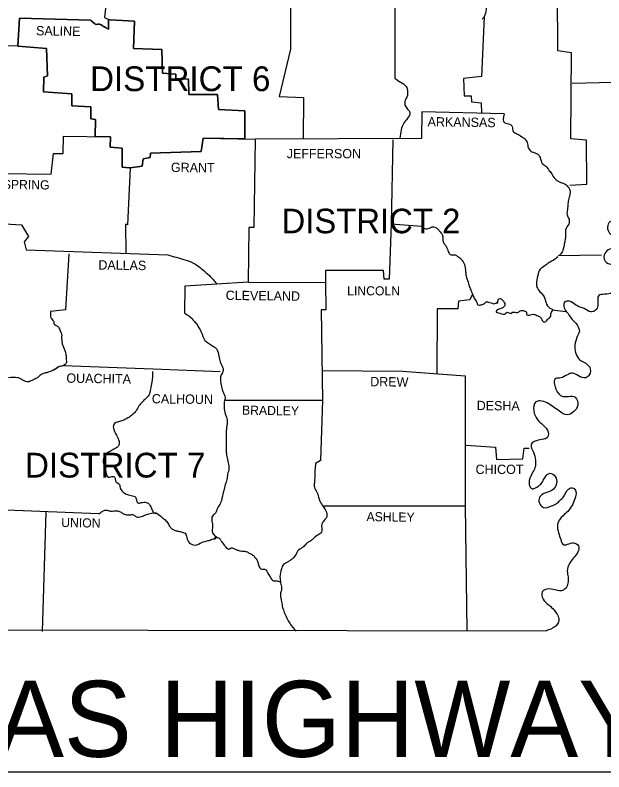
# Model space of a CAD drawing. Extents: x -42408 to 34530, y -43140 to 20491.
# Drawn here: x -16626 to -15135, y 2539 to 4456 of the extents above; entities that cross this region are included whole.
import ezdxf

# ---------------------------------------------------------------- set-up
doc = ezdxf.new("R2010")
doc.units = 0
for name, color, linetype in [('1', 7, 'Continuous'), ('2', 7, 'Continuous'), ('3', 7, 'Continuous'), ('S_MISC_BOUNDARY', 7, 'Continuous')]:
    doc.layers.add(name, color=color, linetype=linetype)

msp = doc.modelspace()

# ---------------------------------------------------------------- linework, layer by layer
at = {"layer": '1'}
for p, q in [((-15250.6, 3847.5), (-15140.6, 3849.1)), ((-17741.9, 2539.3), (-14228.8, 2539.3))]:
    msp.add_line(p, q, dxfattribs=at)
for points in [[(-15743.2, 4605.5), (-15742.1, 4509), (-15664.5, 4507.4), (-15664, 4296)], [(-15952.9, 4581.7), (-15928.7, 4580), (-15928.1, 4369.8), (-15956.8, 4250.4), (-15895.7, 4247.6), (-15896.2, 4142.4)], [(-16215.4, 4527.2), (-16255, 4531.6), (-16253.4, 4516.7), (-16325.5, 4514), (-16327.7, 4492.5), (-16395.4, 4488.7), (-16399.2, 4450.1), (-16389.3, 4445.2), (-16389.3, 4420.6)], [(-15220.9, 4025.3), (-15178, 4028), (-15178.6, 4139.7), (-15218.7, 4142.5), (-15216.5, 4361), (-15251.2, 4365.9), (-15252.3, 4512.9), (-14782.8, 4516.2)], [(-16434.5, 4443), (-16614.4, 4448.5), (-16619.4, 4377.5), (-16839.5, 4378.6), (-16840.6, 4354.9)], [(-15438.3, 4451.8), (-15444.9, 4301), (-15490.1, 4296), (-15489, 4251.5), (-15470.8, 4252), (-15470.2, 4236.6), (-15445.5, 4233.8), (-15444.7, 4207.3)], [(-16385.5, 4444.6), (-16323.8, 4440.8), (-16326, 4372), (-16253.9, 4369.2), (-16252.8, 4309.2), (-16218.7, 4306.5), (-16218.7, 4296), (-16186.8, 4293.8), (-16185.7, 4255.3), (-16113.1, 4255.3), (-16110.9, 4217.3), (-16043.7, 4214), (-16044.3, 4142.5)], [(-16617.9, 4377.4), (-16546.2, 4371.4), (-16544, 4302.1), (-16553.3, 4298.8), (-16554.4, 4261.9), (-16482.3, 4257), (-16482.3, 4226.7), (-16434.5, 4223.9), (-16433.9, 4193.7), (-16422.4, 4192), (-16422.9, 4148.5)], [(-15215.4, 4283.4), (-14905, 4291.1)], [(-15387.7, 4205.8), (-15595.7, 4211.3), (-15596.8, 4143.6), (-16017.8, 4141.9)], [(-16849.4, 4057.7), (-16534.6, 4053.3), (-16528.6, 4105.6), (-16503.8, 4105.6), (-16503.3, 4149.6), (-16384.4, 4148), (-16385.5, 4121.6), (-16354.7, 4119.4), (-16354.7, 4070.9), (-16336, 4069.4)], [(-16334.8, 4069.3), (-16304, 4073.7), (-16301.8, 4092.4), (-16283.7, 4095.7), (-16282.6, 4106.7), (-16154.3, 4110.6), (-16149.4, 4144.1), (-16017.8, 4141.9)], [(-16017.8, 4140.8), (-16021.1, 3918.5), (-16033.8, 3917.9), (-16035.5, 3779.8)], [(-15668.9, 4140.3), (-15673.3, 3927.3), (-15596.8, 3921.2)], [(-16334.8, 4069.3), (-16341.4, 3925.1), (-16346.4, 3926.7), (-16345.9, 3851.9)], [(-16914.4, 3910.8), (-16915.5, 3941.1), (-16906.7, 3941.6), (-16901.2, 4012.6), (-16816.4, 4007.1), (-16818.6, 3963.6), (-16709.1, 3957.6), (-16708.5, 3931.2), (-16609.5, 3925.1), (-16592.4, 3895.4), (-16602.9, 3882.2), (-16597.9, 3861.8), (-16239.1, 3848.6)], [(-15673.3, 3927.3), (-15678.3, 3787.5), (-15690.9, 3787.5), (-15693.1, 3809), (-15839.5, 3809), (-15839.5, 3778.2)], [(-16490, 3851.4), (-16498.3, 3709.9), (-16536.3, 3705.5)], [(-16035.5, 3779.8), (-16115.8, 3774.9)], [(-16035.5, 3779.8), (-15840.6, 3778.7)], [(-15839.5, 3778.7), (-15839, 3709.9), (-15850.5, 3709.4), (-15847.2, 3481)], [(-16114.7, 3774.9), (-16196.2, 3769.9), (-16196.7, 3701.1)], [(-15467.5, 3749.5), (-15474.1, 3734.7), (-15503.3, 3731.9), (-15504.9, 3712.1), (-15557.2, 3712.1), (-15557.7, 3547.6)], [(-15405.8, 3725.3), (-15404.2, 3727), (-15402.5, 3728.6), (-15402.5, 3728.6)], [(-16503.8, 3568.5), (-16276, 3560.2), (-16107, 3553.6)], [(-15848.9, 3555.8), (-15644.7, 3554.2), (-15486.2, 3542.1)], [(-15486.2, 3542.1), (-15486.2, 3212.9), (-15481.8, 2896.5)], [(-16096, 3480.4), (-15847.2, 3481)], [(-15847.2, 3481), (-15852.7, 3328), (-15864.8, 3320.3)], [(-15483.4, 3366.5), (-15409.7, 3362.1), (-15406.4, 3330.2), (-15339.8, 3332.4), (-15337.1, 3359.3), (-15324.4, 3359.3)], [(-17299.1, 3345), (-17298, 2899.8), (-15280.9, 2896.5)], [(-16413.5, 3193.1), (-16648.5, 3201.9), (-16649.6, 3257.5)], [(-15843.9, 3213.5), (-15486.2, 3213.5)], [(-16548.4, 3197), (-16557.2, 2894.8)]]:
    msp.add_lwpolyline(points, dxfattribs=at)
for points in [[(-15444.4, 4504.6), (-15446.6, 4493.6), (-15442.2, 4482.1), (-15434.5, 4478.2), (-15433.4, 4467.2), (-15436.1, 4456.2), (-15438.3, 4451.8), (-15443.3, 4445.2)], [(-16389.3, 4420.6), (-16403.6, 4428.1), (-16411.9, 4433.1), (-16420.7, 4432.5), (-16427.9, 4436.9), (-16434.5, 4443)], [(-14817.5, 4383), (-14830.2, 4367), (-14848.9, 4376.9), (-14848.9, 4390.1), (-14846.1, 4403.9), (-14852.7, 4412.7), (-14864.3, 4408.9), (-14864.3, 4391.8), (-14865.4, 4375.3), (-14868.7, 4351.6), (-14861, 4344.5), (-14843.4, 4342.3), (-14830.7, 4339), (-14823, 4326.3), (-14823.6, 4310.9), (-14829.6, 4296), (-14838.4, 4283.9), (-14852.2, 4279.5), (-14863.2, 4286.7), (-14867.6, 4301), (-14872.6, 4313.6), (-14881.9, 4323), (-14891.8, 4312.5), (-14894, 4293.3), (-14893.5, 4276.8), (-14893.5, 4254.2), (-14879.2, 4239.3), (-14870.4, 4222.3), (-14873.1, 4206.9), (-14883.6, 4188.7), (-14888, 4172.8), (-14892.4, 4151.3), (-14891.8, 4127.6), (-14895.7, 4104.5), (-14903.4, 4089.1), (-14917.7, 4076.4), (-14927, 4068.2), (-14934.7, 4059.9), (-14938.6, 4043.4), (-14941.3, 4031.9), (-14951.8, 4018.1), (-14960.1, 4017), (-14966.7, 4022.5), (-14968.9, 4031.9), (-14968.9, 4041.2), (-14973.3, 4050.6), (-14987, 4054.4), (-14998, 4053.9), (-15003, 4046.2), (-14995.8, 4024.7), (-14993.1, 4011), (-14996.9, 3992.2), (-14994.7, 3990), (-15014.5, 3979.6), (-15030.5, 3977.9), (-15043.7, 3974.1), (-15056.4, 3965.8), (-15062.4, 3953.7), (-15071.2, 3943.8), (-15078.9, 3934.5), (-15089.4, 3930.1), (-15101, 3932.3), (-15116.4, 3933.9), (-15125.2, 3922.9), (-15122.4, 3906.9), (-15112, 3897.6), (-15096.5, 3893.2), (-15080.6, 3894.3), (-15065.2, 3895.9), (-15050.9, 3888.2), (-15053.6, 3873.4), (-15067.4, 3866.2), (-15087.7, 3864), (-15104.3, 3865.7), (-15124.1, 3861.3), (-15134, 3848.6), (-15128.5, 3829.3), (-15107, 3821.6), (-15097.1, 3803.5), (-15096.5, 3786.4), (-15103.7, 3763.8), (-15113.6, 3753.4), (-15132.9, 3749), (-15147.7, 3746.2), (-15149.9, 3720.9), (-15156.5, 3708.3), (-15168.1, 3704.4), (-15184.6, 3712.7), (-15194.5, 3716.5), (-15206.6, 3722), (-15222, 3731.4), (-15233.6, 3729.7), (-15230.3, 3705.5), (-15229.2, 3704.4), (-15216, 3686.2), (-15202.8, 3671.9), (-15196.7, 3654.9)], [(-15664, 4296), (-15650.2, 4286.7), (-15635.9, 4275.7), (-15632, 4260.8), (-15633.1, 4250.4), (-15637.5, 4241.6), (-15638.6, 4227.8), (-15632, 4217.9), (-15626, 4209.6), (-15632, 4194.8), (-15642.5, 4181), (-15648, 4165.6), (-15651.6, 4144.3)], [(-15387.7, 4205.8), (-15386, 4183.2), (-15372.8, 4179.9), (-15367.3, 4173.9), (-15364.6, 4161.2), (-15355.2, 4155.7), (-15342.6, 4148), (-15334.9, 4142.5), (-15329.3, 4133.7), (-15326, 4119.4), (-15317.2, 4110), (-15305.1, 4105.6), (-15296.3, 4095.2), (-15290.8, 4080.3), (-15282, 4073.7), (-15273.2, 4062.1), (-15268.8, 4057.2), (-15261.1, 4044), (-15253.4, 4037.4), (-15247.9, 4033.5), (-15239.1, 4030.8), (-15228.1, 4023.6), (-15220.9, 4012.6), (-15220.9, 4004.3), (-15223.7, 3991.7), (-15225.9, 3978.5), (-15227, 3963.6), (-15228.1, 3950.4), (-15223.1, 3939.4), (-15225.9, 3922.9), (-15231.4, 3914.1), (-15231.9, 3902), (-15233.6, 3883.8), (-15235.8, 3873.4), (-15240.7, 3856.3), (-15247.9, 3847.5)], [(-15596.8, 3921.2), (-15588.6, 3915.7), (-15577, 3916.3), (-15569.3, 3919.6), (-15563.2, 3919), (-15555, 3914.1), (-15549.5, 3907.5), (-15545.6, 3902.5), (-15542.9, 3894.8), (-15542.9, 3887.7), (-15540.1, 3877.8), (-15536.8, 3873.9), (-15532.4, 3866.8), (-15529.7, 3860.2), (-15528, 3855.8), (-15522, 3848.6), (-15516.5, 3849.1), (-15511.5, 3848.6), (-15504.9, 3844.7), (-15495, 3837), (-15493.4, 3834.8), (-15486.7, 3820.5), (-15485.6, 3811.7), (-15484.5, 3800.2), (-15482.3, 3789.2), (-15477.9, 3777.1), (-15475.7, 3768.8), (-15470.8, 3757.2), (-15467.5, 3749.5), (-15463.1, 3739.6), (-15456.5, 3728.6), (-15453.7, 3722), (-15444.4, 3722.6), (-15437.8, 3725.3), (-15432.8, 3729.7), (-15426.8, 3729.2), (-15420.2, 3727), (-15411.4, 3725.3), (-15405.8, 3728.6), (-15403.1, 3730.8), (-15402.5, 3735.8), (-15397.6, 3738.5), (-15392.1, 3734.7), (-15386, 3725.9), (-15386, 3720.4), (-15388.2, 3717.1), (-15395.4, 3712.7), (-15405.3, 3709.4), (-15408, 3705.5), (-15398.7, 3701.1), (-15383.8, 3700), (-15380, 3703.3), (-15370.1, 3700.6), (-15366.2, 3703.3), (-15353, 3702.8), (-15347, 3707.2), (-15334.9, 3706.6), (-15331, 3703.9), (-15331, 3698.9), (-15321.1, 3696.7), (-15313.9, 3698.4), (-15304.6, 3695.6), (-15296.3, 3691.2), (-15291.9, 3685.1), (-15286.4, 3678.5), (-15281.5, 3680.2), (-15277.6, 3685.1), (-15269.4, 3693.9), (-15269.4, 3699.5), (-15267.2, 3703.3), (-15264.4, 3708.8)], [(-16239.1, 3848.6), (-16196.2, 3836.5), (-16174.1, 3828.2), (-16152.1, 3812.3), (-16134, 3796.3), (-16115.8, 3776)], [(-15251.7, 3844.2), (-15263.3, 3834.8), (-15273.2, 3829.3), (-15283.7, 3821.6), (-15296.3, 3812.3), (-15302.4, 3796.3), (-15305.7, 3774.3), (-15301.3, 3761.1), (-15291.4, 3749.5), (-15284.8, 3740.2), (-15279.8, 3723.7), (-15267.7, 3712.1), (-15263.9, 3710.5)], [(-16536.3, 3705.5), (-16536.3, 3695), (-16532.4, 3685.1), (-16528.6, 3680.7), (-16526.9, 3673.6), (-16522, 3670.3), (-16514.8, 3663.7), (-16511, 3654.3), (-16508.2, 3648.3), (-16508.2, 3640.6), (-16507.7, 3632.9), (-16506.6, 3623.5), (-16500, 3607), (-16498.3, 3600.4), (-16497.2, 3594.9), (-16496.6, 3585.5), (-16496.6, 3574.5), (-16503.8, 3568.5)], [(-16196.7, 3701.1), (-16184, 3692.8), (-16173.6, 3681.8), (-16165.9, 3673.6), (-16160.9, 3664.2), (-16154.3, 3653.2), (-16145, 3632.3), (-16136.7, 3625.2), (-16125.2, 3618), (-16118, 3613), (-16110.9, 3597.1), (-16107.5, 3581.1), (-16101.5, 3566.8), (-16098.7, 3555.8), (-16103.7, 3544.8), (-16104.8, 3522.8), (-16101.5, 3507.9), (-16097.1, 3496.9), (-16094.3, 3484.3), (-16096, 3480.4)], [(-15196.7, 3654.9), (-15202.2, 3642.2), (-15208.3, 3620.2), (-15206.6, 3601.5), (-15198.4, 3585.5), (-15185.2, 3576.7), (-15170.8, 3564.1), (-15171.9, 3544.8), (-15180.2, 3537.6), (-15199.5, 3542.6), (-15214.3, 3549.2), (-15227, 3545.4), (-15244, 3537.1), (-15256.7, 3535.4), (-15256.2, 3509), (-15239.1, 3490.3), (-15224.2, 3490.3), (-15207.2, 3488.1), (-15201.1, 3468.3), (-15211, 3451.8), (-15227.5, 3443.5), (-15248.4, 3453.4), (-15263.3, 3463.9), (-15278.2, 3473.8), (-15296.9, 3478.8), (-15307.3, 3476.6), (-15312.3, 3453.4), (-15303.5, 3432.5), (-15289.2, 3418.2), (-15276, 3399.5), (-15278.2, 3385.8), (-15288.1, 3381.9), (-15305.7, 3378), (-15316.1, 3372.5), (-15318.9, 3368.1), (-15313.4, 3349.4), (-15308.4, 3329.1), (-15308.4, 3313.7), (-15314.5, 3299.3), (-15323.8, 3277.3), (-15322.7, 3263), (-15316.1, 3256.4), (-15307.9, 3258.6), (-15296.9, 3266.3), (-15289.7, 3275.1), (-15283.7, 3286.1), (-15272.1, 3295.5), (-15257.8, 3287.2), (-15254.5, 3270.2), (-15262.8, 3255.3), (-15274.3, 3248.7), (-15288.6, 3243.2), (-15299.1, 3231.1), (-15296.3, 3216.8), (-15288.1, 3209.1), (-15267.7, 3212.9), (-15253.9, 3219), (-15246.2, 3226.7), (-15236.9, 3236.1), (-15231.9, 3245.4), (-15224.8, 3255.3), (-15212.1, 3258.1), (-15206.1, 3249.8), (-15208.3, 3231.1), (-15216, 3213.5), (-15226.4, 3198.6), (-15238, 3188.2), (-15252.3, 3165.6), (-15249.5, 3144.7), (-15244, 3127.6), (-15236.3, 3114.4), (-15223.1, 3117.2), (-15208.3, 3118.8), (-15199.5, 3111.7), (-15200.6, 3096.3), (-15211.6, 3081.4), (-15222, 3067.1), (-15227.5, 3047.3), (-15225.3, 3033.5), (-15225.3, 3020.9), (-15229.7, 3007.1), (-15237.4, 2999.4), (-15257.8, 3000), (-15279.3, 3002.2), (-15290.8, 2995.6), (-15288.6, 2976.8), (-15276, 2963.1), (-15267.2, 2955.9), (-15254.5, 2940.5), (-15249, 2927.9), (-15250.6, 2916.8), (-15258.4, 2907.5), (-15280.9, 2896.5)], [(-16514.3, 3566.3), (-16528.6, 3556.9), (-16539.6, 3552.5), (-16547.8, 3549.8), (-16555.5, 3547.6), (-16565.4, 3541), (-16573.1, 3535.4), (-16583.6, 3530.5), (-16593.5, 3527.2), (-16605.6, 3531), (-16612.2, 3534.9), (-16619.4, 3537.6), (-16642.5, 3537.6)], [(-16528.6, 3556.9), (-16514.3, 3566.3), (-16503.8, 3568.5)], [(-16278.2, 3553.6), (-16279.3, 3526.1), (-16283.1, 3509), (-16287, 3493.6), (-16295.2, 3484.8), (-16304, 3476), (-16312.3, 3466.1), (-16319.4, 3454), (-16326.6, 3446.3), (-16335.9, 3438.6), (-16345.3, 3433.1), (-16355.8, 3428.1), (-16367.3, 3425.4), (-16375.6, 3419.3), (-16376.1, 3406.1), (-16366.8, 3387.4), (-16363.5, 3378.6), (-16362.4, 3368.1), (-16366.2, 3362.1), (-16375, 3357.1), (-16385.5, 3351.1), (-16394.8, 3345.6), (-16401.4, 3336.2), (-16402.5, 3323.6), (-16398.1, 3308.7), (-16396.5, 3299.9), (-16389.3, 3286.1), (-16383.8, 3286.7), (-16373.9, 3286.1), (-16372.8, 3283.4), (-16372.3, 3280.6), (-16370.1, 3273.5), (-16361.8, 3267.4), (-16360.7, 3261.9), (-16355.8, 3251.5), (-16347.5, 3244.3), (-16341.4, 3242.1), (-16328.8, 3238.3), (-16322.2, 3236.6), (-16315, 3220.6), (-16306.2, 3221.2), (-16299.6, 3222.3), (-16288.6, 3219.5), (-16283.7, 3212.9), (-16278.7, 3201.9), (-16272.1, 3194.2), (-16267.7, 3194.2)], [(-16096, 3480.4), (-16093.8, 3446.3), (-16088.8, 3429.8), (-16090.5, 3412.2), (-16091, 3395.1), (-16091, 3379.7), (-16091, 3364.8), (-16091, 3349.4), (-16089.9, 3338.4), (-16086.1, 3322.5), (-16084.4, 3307.6), (-16087.7, 3293.3), (-16089.4, 3280.1), (-16093.8, 3266.9), (-16097.6, 3252), (-16102, 3232.8), (-16105.9, 3220.1), (-16113.6, 3206.9), (-16118.6, 3194.8), (-16126.3, 3187.1), (-16127.4, 3173.9), (-16125.7, 3161.8), (-16126.8, 3150.7), (-16123, 3140.3), (-16113.1, 3133.1)], [(-15864.8, 3320.3), (-15866.5, 3303.2), (-15867, 3287.2), (-15868.1, 3271.8), (-15868.1, 3260.3), (-15861.5, 3247.6), (-15857.7, 3235.5), (-15853.8, 3225), (-15846.1, 3211.3), (-15839, 3200.8), (-15836.8, 3186), (-15841.2, 3178.3), (-15849.4, 3166.7), (-15850, 3145.8), (-15859.9, 3139.2), (-15872.5, 3128.2), (-15879.7, 3123.2), (-15887.4, 3118.3), (-15895.7, 3109.5), (-15907.8, 3101.2), (-15916.6, 3087.5), (-15926.5, 3077), (-15934.7, 3071.5), (-15946.3, 3064.3), (-15951.2, 3053.3), (-15955.1, 3033), (-15953.4, 3018.1), (-15951.2, 3004.9), (-15954, 2988.4), (-15951.2, 2970.2), (-15948.5, 2955.9), (-15944.1, 2943.3), (-15938, 2929), (-15930.3, 2915.7), (-15913.8, 2895.4)], [(-16413.5, 3193.1), (-16404.7, 3199.2), (-16396.5, 3202.5), (-16388.2, 3200.8), (-16379.4, 3199.7), (-16371.7, 3200.8), (-16361.8, 3199.2), (-16353.6, 3194.2), (-16344.2, 3190.4), (-16334.8, 3190.4), (-16326.6, 3190.4), (-16319.4, 3185.4), (-16306.2, 3186), (-16295.2, 3190.4), (-16284.2, 3193.7), (-16269.4, 3195.3), (-16256.1, 3186), (-16246.8, 3178.3), (-16239.1, 3169.5), (-16233.6, 3159.6), (-16227.5, 3154.1), (-16217.6, 3150.2), (-16209.9, 3148.5), (-16200.6, 3145.8), (-16195.6, 3143.6), (-16191.2, 3133.1), (-16184, 3118.8), (-16170.3, 3113.9), (-16153.2, 3120.5), (-16139.5, 3124.3), (-16129.6, 3127.6), (-16123.5, 3129.8), (-16118, 3130.4), (-16119.7, 3131.5), (-16113.1, 3133.1), (-16107, 3128.7), (-16103.1, 3122.7), (-16096.5, 3113.9), (-16090.5, 3106.2), (-16084.4, 3103.4), (-16078.4, 3106.7), (-16070.1, 3104), (-16063, 3101.2), (-16054.7, 3099), (-16047.6, 3098.5), (-16038.2, 3096.3), (-16031, 3092.4), (-16024.4, 3088.6), (-16017.8, 3081.4), (-16011.2, 3070.4), (-16009, 3061.6), (-16001.3, 3052.8), (-15994.2, 3052.8), (-15983.7, 3038.5), (-15979.9, 3033), (-15971.6, 3023.1), (-15965.6, 3023.1), (-15954, 3020.9)]]:
    msp.add_spline(points, degree=3, dxfattribs=at)
at = {"layer": '3'}
msp.add_line((-15265.5, 3709.9), (-15230.8, 3705.5), dxfattribs=at)
at = {"layer": 'S_MISC_BOUNDARY'}
for p, q in [((-16614.4, 4448.5), (-16619.4, 4377.5)), ((-16434.5, 4443), (-16614.4, 4448.5)), ((-16389.3, 4445.2), (-16389.3, 4420.6)), ((-16326, 4372), (-16323.8, 4440.8)), ((-16389.3, 4420.6), (-16394.3, 4423.4)), ((-16619.4, 4377.5), (-16617.9, 4377.4)), ((-16617.9, 4377.4), (-16546.2, 4371.4)), ((-16253.9, 4369.2), (-16326, 4372)), ((-16186.8, 4293.8), (-16218.7, 4296)), ((-16482.3, 4226.7), (-16434.5, 4223.9)), ((-16434.5, 4223.9), (-16433.9, 4193.7)), ((-16304, 4073.7), (-16301.8, 4092.4)), ((-16301.8, 4092.4), (-16283.7, 4095.7)), ((-16354.7, 4070.9), (-16336, 4069.4)), ((-16336, 4069.4), (-16334.8, 4069.3)), ((-16334.8, 4069.3), (-16304, 4073.7))]:
    msp.add_line(p, q, dxfattribs=at)
for points in [[(-16619.4, 4377.5), (-16614.4, 4448.5), (-16434.5, 4443), (-16424.3, 4434.7), (-16420.7, 4432.5), (-16416.3, 4432.8), (-16411.9, 4433.1), (-16389.3, 4420.6), (-16389.3, 4445.2), (-16385.5, 4444.6), (-16323.8, 4440.8), (-16326, 4372), (-16253.9, 4369.2), (-16253.4, 4339.2), (-16252.8, 4309.2), (-16218.6, 4306.5), (-16218.8, 4296), (-16186.7, 4293.8), (-16185.7, 4255.3), (-16113.1, 4255.3), (-16110.9, 4217.3), (-16043.7, 4214), (-16044.3, 4142.5), (-16149.4, 4144.1), (-16154.3, 4110.6), (-16282.6, 4106.7), (-16283.7, 4095.7), (-16301.8, 4092.4), (-16304, 4073.7), (-16334.8, 4069.3), (-16336, 4069.4), (-16354.7, 4070.9), (-16354.7, 4119.4), (-16385.5, 4121.6), (-16384.4, 4148), (-16422.9, 4148.5), (-16422.4, 4192), (-16433.9, 4193.7), (-16434.5, 4223.9), (-16482.3, 4226.7), (-16482.3, 4257), (-16554.4, 4261.9), (-16553.3, 4298.8), (-16544, 4302.1), (-16546.2, 4371.4), (-16619.4, 4377.5)], [(-16411, 4432.6), (-16411.9, 4433.1), (-16416.3, 4432.8), (-16416.6, 4432.8)], [(-16323.8, 4440.8), (-16385.5, 4444.6), (-16389.3, 4445.2)], [(-16546.2, 4371.4), (-16544, 4302.1), (-16553.3, 4298.8), (-16554.4, 4261.9)], [(-16218.7, 4296), (-16218.7, 4306.5), (-16252.8, 4309.2), (-16253.4, 4339.2), (-16253.9, 4369.2)], [(-16113.1, 4255.3), (-16185.7, 4255.3), (-16186.8, 4293.8)], [(-16554.4, 4261.9), (-16482.3, 4257), (-16482.3, 4226.7)], [(-16283.7, 4095.7), (-16282.6, 4106.7), (-16154.3, 4110.6), (-16149.4, 4144.1), (-16044.3, 4142.5), (-16043.7, 4214), (-16110.9, 4217.3), (-16113.1, 4255.3)], [(-16433.9, 4193.7), (-16422.4, 4192), (-16422.9, 4148.5)], [(-16422.9, 4148.5), (-16384.4, 4148), (-16385.5, 4121.6)], [(-16385.5, 4121.6), (-16354.7, 4119.4), (-16354.7, 4070.9)]]:
    msp.add_lwpolyline(points, dxfattribs=at)
msp.add_open_spline([(-16416.6, 4432.8), (-16418, 4432.4), (-16419.4, 4432), (-16420.7, 4432.5), (-16423.3, 4433.6), (-16425.7, 4435.1), (-16427.9, 4436.9), (-16430.2, 4438.9), (-16432.4, 4440.8), (-16434.5, 4443)], degree=3, dxfattribs=at)
msp.add_spline([(-16394.3, 4423.4), (-16399, 4425.7), (-16403.6, 4428.1), (-16404.6, 4428.6), (-16405.5, 4429.2), (-16407.3, 4430.3), (-16409.1, 4431.5), (-16411, 4432.6)], degree=3, dxfattribs=at)

# ---------------------------------------------------------------- texts
at = {"layer": '2'}
for s, height, rotation, p in [('SALINE', 23.67, 359.1491, (-16573.1, 4405)), ('ARKANSAS', 23.66, 359.2678, (-15581.4, 4174.4)), ('GRANT', 23.67, 359.4032, (-16231.4, 4058.8)), ('HOT SPRING', 23.11, 359.2216, (-16731.1, 4017)), ('DALLAS', 23.66, 359.2462, (-16415.2, 3811.7)), ('CLEVELAND', 23.67, 359.3377, (-16092.7, 3734.7)), ('OUACHITA', 23.67, 359.2043, (-16496.1, 3525)), ('DREW', 23.66, 359.2258, (-15726.7, 3516.2)), ('CALHOUN', 23.67, 359.3634, (-16279.8, 3472.7)), ('DESHA', 23.66, 359.3704, (-15457, 3455.6)), ('BRADLEY', 23.11, 359.1449, (-16051.4, 3444.1)), ('UNION', 23.11, 358.9584, (-16509.3, 3159.6)), ('ASHLEY', 23.11, 359.2361, (-15736.1, 3174.4))]:
    msp.add_text(s, height=height, rotation=rotation, dxfattribs=at).set_placement(p)
for s, height, p in [('JEFFERSON', 23.67, (-15938, 4093.5)), ('LINCOLN', 23.11, (-15785, 3746.2)), ('CHICOT', 23.67, (-15459.8, 3293.8)), ('ARKANSAS HIGHWAY DISTRICT 6', 192.623, (-17733.2, 2577.3))]:
    msp.add_text(s, height=height, dxfattribs=at).set_placement(p)
at = {"layer": '3'}
for s, height, p in [('DISTRICT 6', 62.74, (-16436.1, 4263.6)), ('DISTRICT 2', 62.19, (-15951.2, 3903.6)), ('DISTRICT 7', 62.74, (-16600.8, 3284.8))]:
    msp.add_text(s, height=height, dxfattribs=at).set_placement(p)

doc.saveas('drawing.dxf')
